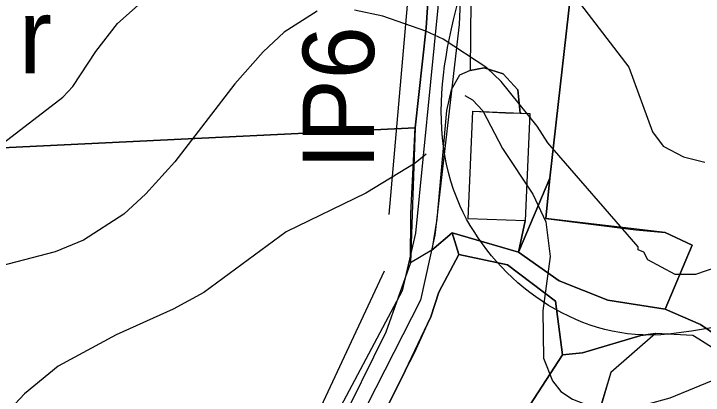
# Model space of a CAD drawing. Extents: x -684583 to -680383, y -1157874 to -1154904.
# Drawn here: x -683367.4 to -683174.3, y -1156765.6 to -1156658.6 of the extents above; entities that cross this region are included whole.
import ezdxf

# ---------------------------------------------------------------- set-up
doc = ezdxf.new("R2010")
doc.units = 0
for name, color, linetype in [('01_OBVOD PÚ', 7, 'Continuous'), ('01_VRSTEVNICE', 7, 'Continuous'), ('02_KULTURY STAV', 7, 'Continuous'), ('03_PC_OBJEKTY_NÁVRH', 7, 'Continuous'), ('03_PC_STAV', 7, 'Continuous'), ('06_BIOGEOGRAFIE', 7, 'Continuous'), ('06_ÚSES_IP', 7, 'Continuous')]:
    doc.layers.add(name, color=color, linetype=linetype)

msp = doc.modelspace()

# ---------------------------------------------------------------- linework, layer by layer
at = {"layer": '01_OBVOD PÚ'}
for points in [[(-683210.97, -1156648.47), (-683217.31, -1156704.71), (-683226.06, -1156725.48), (-683244.68, -1156720.06), (-683242.83, -1156726.19), (-683248.39, -1156736.74), (-683250.62, -1156743.63), (-683257.82, -1156758.78), (-683265.82, -1156774.93), (-683276.42, -1156793.19), (-683279.3, -1156797.4), (-683289.61, -1156819.17), (-683290.39, -1156823.72), (-683290.45, -1156831.08), (-683286.38, -1156838.25), (-683294.66, -1156834.61), (-683303.58, -1156846.39), (-683306.38, -1156857.92), (-683311.13, -1156860.63), (-683323.26, -1156864.81), (-683340.48, -1156874.45), (-683352.99, -1156875.58), (-683357.1, -1156874.68), (-683383.68, -1156876.28)], [(-683265.82, -1156774.93), (-683257.82, -1156758.78), (-683255.21, -1156753.74), (-683250.62, -1156743.63), (-683248.39, -1156736.74), (-683242.83, -1156726.19), (-683244.68, -1156720.06), (-683226.06, -1156725.48), (-683220.02, -1156711.16), (-683217.31, -1156704.71), (-683210.97, -1156648.47)]]:
    msp.add_lwpolyline(points, dxfattribs=at)
at = {"layer": '01_VRSTEVNICE'}
for points in [[(-683572.71, -1156728.24), (-683566.43, -1156735.37), (-683555.73, -1156744.22), (-683545.75, -1156750.63), (-683513.23, -1156768.46), (-683483.13, -1156790.29), (-683477.14, -1156792.86), (-683473.14, -1156793.43), (-683469.43, -1156792.43), (-683463.73, -1156787.01), (-683451.18, -1156770.6), (-683440.48, -1156760.62), (-683425.36, -1156750.21), (-683417.94, -1156744.07), (-683412.38, -1156736.8), (-683403.39, -1156727.67), (-683391.55, -1156717.97), (-683375.29, -1156698.57), (-683353.75, -1156682.02), (-683350.9, -1156679.03), (-683344.48, -1156669.18), (-683338.35, -1156661.34), (-683330.07, -1156653.92)], [(-683210.82, -1156653.07), (-683195.13, -1156673.61), (-683188.57, -1156691.72), (-683185.57, -1156695.72), (-683179.87, -1156698.71), (-683173.88, -1156700.28)], [(-683282.43, -1156657.92), (-683291.7, -1156663.76), (-683297.55, -1156669.33), (-683305.54, -1156678.31), (-683322.37, -1156700.14), (-683330.5, -1156709.12), (-683336.63, -1156714.83), (-683347.9, -1156722.11), (-683355.89, -1156725.39), (-683371.3, -1156729.38)], [(-683153.91, -1156723.96), (-683176.45, -1156731.8), (-683182.15, -1156731.8), (-683189.85, -1156727.67), (-683190.99, -1156725.53), (-683192.56, -1156724.82), (-683192.56, -1156723.96), (-683217.81, -1156694.86), (-683220.81, -1156690.15), (-683230.93, -1156677.6), (-683234.93, -1156673.75), (-683247.2, -1156665.76), (-683252.05, -1156663.48), (-683264.03, -1156659.34), (-683272.02, -1156657.63)], [(-683241.06, -1156681.59), (-683238.92, -1156682.74), (-683236.07, -1156685.88), (-683230.51, -1156696.43), (-683222.09, -1156709.27), (-683218.38, -1156716.97), (-683217.24, -1156726.67), (-683219.24, -1156741.93), (-683219.09, -1156755.2), (-683216.53, -1156761.62), (-683214.24, -1156764.61), (-683210.96, -1156766.75), (-683207.54, -1156768.04), (-683198.98, -1156768.89), (-683190.42, -1156768.18), (-683183.58, -1156766.33), (-683154.76, -1156754.49)], [(-683251.9, -1156698), (-683255.04, -1156700.57), (-683268.88, -1156708.98), (-683291.13, -1156719.82), (-683314.24, -1156736.8), (-683322.8, -1156741.51), (-683338.77, -1156748.64), (-683355.04, -1156757.48), (-683364.45, -1156765.18), (-683372.44, -1156773.74), (-683379.43, -1156782.44), (-683386.27, -1156788.72), (-683404.1, -1156802.41), (-683427.5, -1156823.24), (-683441.76, -1156833.08), (-683450.18, -1156837.65), (-683459.17, -1156841.21), (-683470.58, -1156843.21), (-683479.13, -1156843.21), (-683493.11, -1156839.93), (-683499.58, -1156836.93), (-683505.52, -1156833.22)]]:
    msp.add_lwpolyline(points, dxfattribs=at)
at = {"layer": '02_KULTURY STAV'}
for points in [[(-683239.6, -1156674.58), (-683235.72, -1156673.83), (-683230.34, -1156675.52), (-683226.22, -1156679.98), (-683225.59, -1156686.55), (-683222.89, -1156686.61), (-683224.21, -1156716.74), (-683226.06, -1156725.48), (-683217.31, -1156704.71), (-683210.97, -1156648.47), (-683204.31, -1156597.48), (-683205.51, -1156585.15), (-683210.65, -1156580.69), (-683219.53, -1156585.09), (-683230.72, -1156587.44), (-683235.71, -1156592.49), (-683236.8, -1156599.48), (-683237.66, -1156611.13), (-683239.01, -1156630.41), (-683239.35, -1156645)], [(-683225.59, -1156686.55), (-683226.22, -1156679.98), (-683230.34, -1156675.52), (-683235.72, -1156673.83), (-683239.6, -1156674.58), (-683242.64, -1156675.89), (-683244.96, -1156680.01), (-683246.27, -1156685.76), (-683248.95, -1156716.28), (-683250.37, -1156724.9), (-683244.68, -1156720.06), (-683226.06, -1156725.48), (-683224.21, -1156716.74), (-683240.2, -1156716.13), (-683238.88, -1156685.99), (-683229.72, -1156686.37)], [(-683238.88, -1156685.99), (-683222.89, -1156686.61), (-683224.21, -1156716.74), (-683240.2, -1156716.13)], [(-683461.57, -1156698.06), (-683456.76, -1156701.28), (-683452.45, -1156702.26), (-683445.89, -1156701.53), (-683440.19, -1156699.57), (-683255.02, -1156690.63), (-683256.28, -1156728.52), (-683263.19, -1156747.9), (-683277, -1156775.83), (-683293.02, -1156802.11), (-683296.59, -1156809.49), (-683303.1, -1156808.51), (-683311.62, -1156809.46), (-683470.65, -1156788)], [(-683226.06, -1156725.48), (-683217.31, -1156704.71), (-683218.43, -1156716.08), (-683193.24, -1156719.24), (-683185.03, -1156719.99), (-683177.41, -1156723.52), (-683184.95, -1156741.48), (-683201.02, -1156738.96), (-683214.69, -1156733.53)], [(-683283.43, -1156837.62), (-683286.38, -1156838.25), (-683290.45, -1156831.08), (-683290.39, -1156823.72), (-683289.61, -1156819.17), (-683279.3, -1156797.4), (-683276.42, -1156793.19), (-683265.82, -1156774.93), (-683257.82, -1156758.78), (-683250.62, -1156743.63), (-683248.39, -1156736.74), (-683242.83, -1156726.19), (-683229.14, -1156729.09), (-683215.74, -1156739.23), (-683213.74, -1156754.24), (-683245.46, -1156803.25), (-683258.9, -1156818.99), (-683259.64, -1156819.85), (-683268.25, -1156811.84), (-683280.43, -1156825.81), (-683276.1, -1156829.55)], [(-683258.9, -1156818.99), (-683245.46, -1156803.25), (-683213.74, -1156754.24), (-683208.11, -1156753.73), (-683191.78, -1156748.91), (-683187.69, -1156748.26), (-683200.25, -1156759.23), (-683208.62, -1156787.75), (-683212.92, -1156787.19), (-683228.7, -1156785.15), (-683233.69, -1156792.8), (-683239.98, -1156801.63), (-683256.76, -1156820.81)]]:
    msp.add_lwpolyline(points, close=True, dxfattribs=at)
for points in [[(-683250.43, -1156639.58), (-683251.92, -1156662.61), (-683255.02, -1156690.63), (-683440.19, -1156699.57), (-683446.37, -1156696.93), (-683454.14, -1156695.86), (-683458.28, -1156696.29), (-683461.57, -1156698.06), (-683470.65, -1156788), (-683481.96, -1156770.49), (-683502.22, -1156751.48), (-683504.93, -1156744.71), (-683507.26, -1156741.71), (-683509.77, -1156740.38), (-683516.1, -1156730.82), (-683515.85, -1156721.2), (-683508.45, -1156703.51), (-683505.19, -1156687.78), (-683500.09, -1156674.67), (-683485.88, -1156655.07)], [(-683239.35, -1156645), (-683239.6, -1156674.58), (-683242.64, -1156675.89), (-683244.96, -1156680.01), (-683246.27, -1156685.76), (-683248.95, -1156716.28), (-683250.37, -1156724.9), (-683256.28, -1156728.52), (-683256.2, -1156714.69), (-683255.02, -1156690.63), (-683251.92, -1156662.61), (-683250.43, -1156639.58)], [(-683150.31, -1156762.56), (-683175.1, -1156745.81), (-683184.95, -1156741.48), (-683177.41, -1156723.52), (-683185.03, -1156719.99), (-683218.43, -1156716.08), (-683217.31, -1156704.71), (-683210.97, -1156648.47)], [(-683265.82, -1156774.93), (-683257.82, -1156758.78), (-683250.62, -1156743.63), (-683248.39, -1156736.74), (-683242.83, -1156726.19), (-683244.68, -1156720.06), (-683250.37, -1156724.9), (-683256.28, -1156728.52), (-683263.19, -1156747.9), (-683277, -1156775.83)], [(-683151.37, -1156765.19), (-683175.6, -1156749.85), (-683177.22, -1156748.82), (-683187.69, -1156748.26), (-683191.78, -1156748.91), (-683208.11, -1156753.73), (-683213.74, -1156754.24), (-683215.74, -1156739.23), (-683229.14, -1156729.09), (-683242.83, -1156726.19), (-683244.68, -1156720.06), (-683226.06, -1156725.48), (-683214.69, -1156733.53), (-683201.02, -1156738.96), (-683184.95, -1156741.48), (-683175.1, -1156745.81), (-683150.31, -1156762.56)], [(-683151.37, -1156765.19), (-683175.6, -1156749.85), (-683177.22, -1156748.82), (-683187.69, -1156748.26), (-683200.25, -1156759.23), (-683206.23, -1156778.94), (-683208.62, -1156787.75), (-683195.55, -1156789.46), (-683196.55, -1156797.7), (-683210.82, -1156795.88), (-683213.21, -1156804.71), (-683205.38, -1156805.73), (-683205.96, -1156813.13), (-683215.13, -1156837.51), (-683213.52, -1156838.11), (-683193.32, -1156821.98), (-683177.24, -1156805.79), (-683191.15, -1156790.82), (-683194.84, -1156787.91), (-683194.12, -1156786.48), (-683187.48, -1156791.48), (-683166.97, -1156810.17)]]:
    msp.add_lwpolyline(points, dxfattribs=at)
at = {"layer": '03_PC_OBJEKTY_NÁVRH'}
msp.add_lwpolyline([(-683174.65, -1155937.35), (-683210.22, -1156053.67), (-683213.15, -1156063.25), (-683222.33, -1156079.87), (-683239.53, -1156106.26), (-683245.78, -1156132.85), (-683252.62, -1156185.25), (-683250.28, -1156264.23), (-683244.8, -1156283.2), (-683228.39, -1156329.92), (-683241.68, -1156432.76), (-683244.02, -1156480.07), (-683236.01, -1156514.67), (-683236.01, -1156553.77), (-683245.39, -1156601.08), (-683248.71, -1156657), (-683254.96, -1156720.15), (-683258.68, -1156736.37), (-683280.56, -1156777.62), (-683294.63, -1156809.69), (-683298.73, -1156825.13), (-683296.59, -1156836.67)], dxfattribs=at)
at = {"layer": '03_PC_STAV'}
msp.add_lwpolyline([(-683239.83, -1156280.24), (-683222.66, -1156329.19), (-683228.08, -1156374.72), (-683235.8, -1156433.94), (-683237.9, -1156479.43), (-683235.03, -1156493.24), (-683229.88, -1156514.73), (-683229.88, -1156553.84), (-683240.11, -1156600.78), (-683242.65, -1156661.68), (-683249.53, -1156720.73), (-683253.54, -1156738.98), (-683290.99, -1156812.56), (-683293.44, -1156824.43), (-683291.03, -1156839.88), (-683283.21, -1156847.9)], dxfattribs=at)
at = {"layer": '06_BIOGEOGRAFIE'}
for points in [[(-682624.87, -1154935.44), (-682669.05, -1155140.04), (-682739.65, -1155253.72), (-682834.36, -1155382.91), (-682941.12, -1155661.96), (-683008.28, -1155760.14), (-683056.49, -1155810.09), (-683084.04, -1155808.37), (-683154.45, -1155886.49), (-683231.94, -1156062.19), (-683280.08, -1156211.64), (-683362.74, -1156430.39), (-683497.05, -1156731.83), (-683541.82, -1156781.78), (-683638.25, -1156792.12), (-683701.96, -1156768), (-683817.33, -1156693.94)], [(-683099.47, -1156889.99), (-683108.08, -1156852.09), (-683133.91, -1156841.76), (-683133.91, -1156814.2), (-683132.19, -1156784.91), (-683147.69, -1156747.02), (-683189.01, -1156748.74), (-683242.39, -1156712.57), (-683235.51, -1156631.61), (-683171.79, -1156531.71), (-683097.75, -1156511.04), (-683004.76, -1156526.54), (-682887.67, -1156483.48), (-682868.73, -1156459.36), (-682823.96, -1156452.47), (-682839.46, -1156516.2), (-682863.56, -1156605.77), (-682887.67, -1156736.68), (-682923.83, -1156891.71), (-682934.16, -1156915.82), (-682965.16, -1156929.6), (-683004.76, -1156926.16)], [(-683605.53, -1156693.94), (-683552.15, -1156773.17), (-683505.66, -1156862.74), (-683385.12, -1156876.52), (-683240.48, -1156867.91), (-682983.91, -1156935.09), (-682923.69, -1156998.38), (-682921.97, -1157094.84), (-682923.69, -1157198.19), (-682892.7, -1157272.26), (-682746.33, -1157329.1), (-682572.41, -1157337.72), (-682417.44, -1157289.49), (-682386.73, -1157266.62)]]:
    msp.add_spline(points, degree=3, dxfattribs=at)
at = {"layer": '06_ÚSES_IP'}
for points in [[(-683262.28, -1156714.94), (-683253.85, -1156617.71), (-683245.49, -1156518.54), (-683401.74, -1156519.94)], [(-683294.49, -1156797.02), (-683263.65, -1156730.72)]]:
    msp.add_lwpolyline(points, dxfattribs=at)

# ---------------------------------------------------------------- texts
at = {"layer": '02_KULTURY STAV'}
msp.add_text('r', height=21, dxfattribs=at).set_placement((-683366.05, -1156675.34))
at = {"layer": '06_ÚSES_IP'}
msp.add_text('IP6', height=20, rotation=90, dxfattribs=at).set_placement((-683266.52, -1156702.27))

doc.saveas('drawing.dxf')
